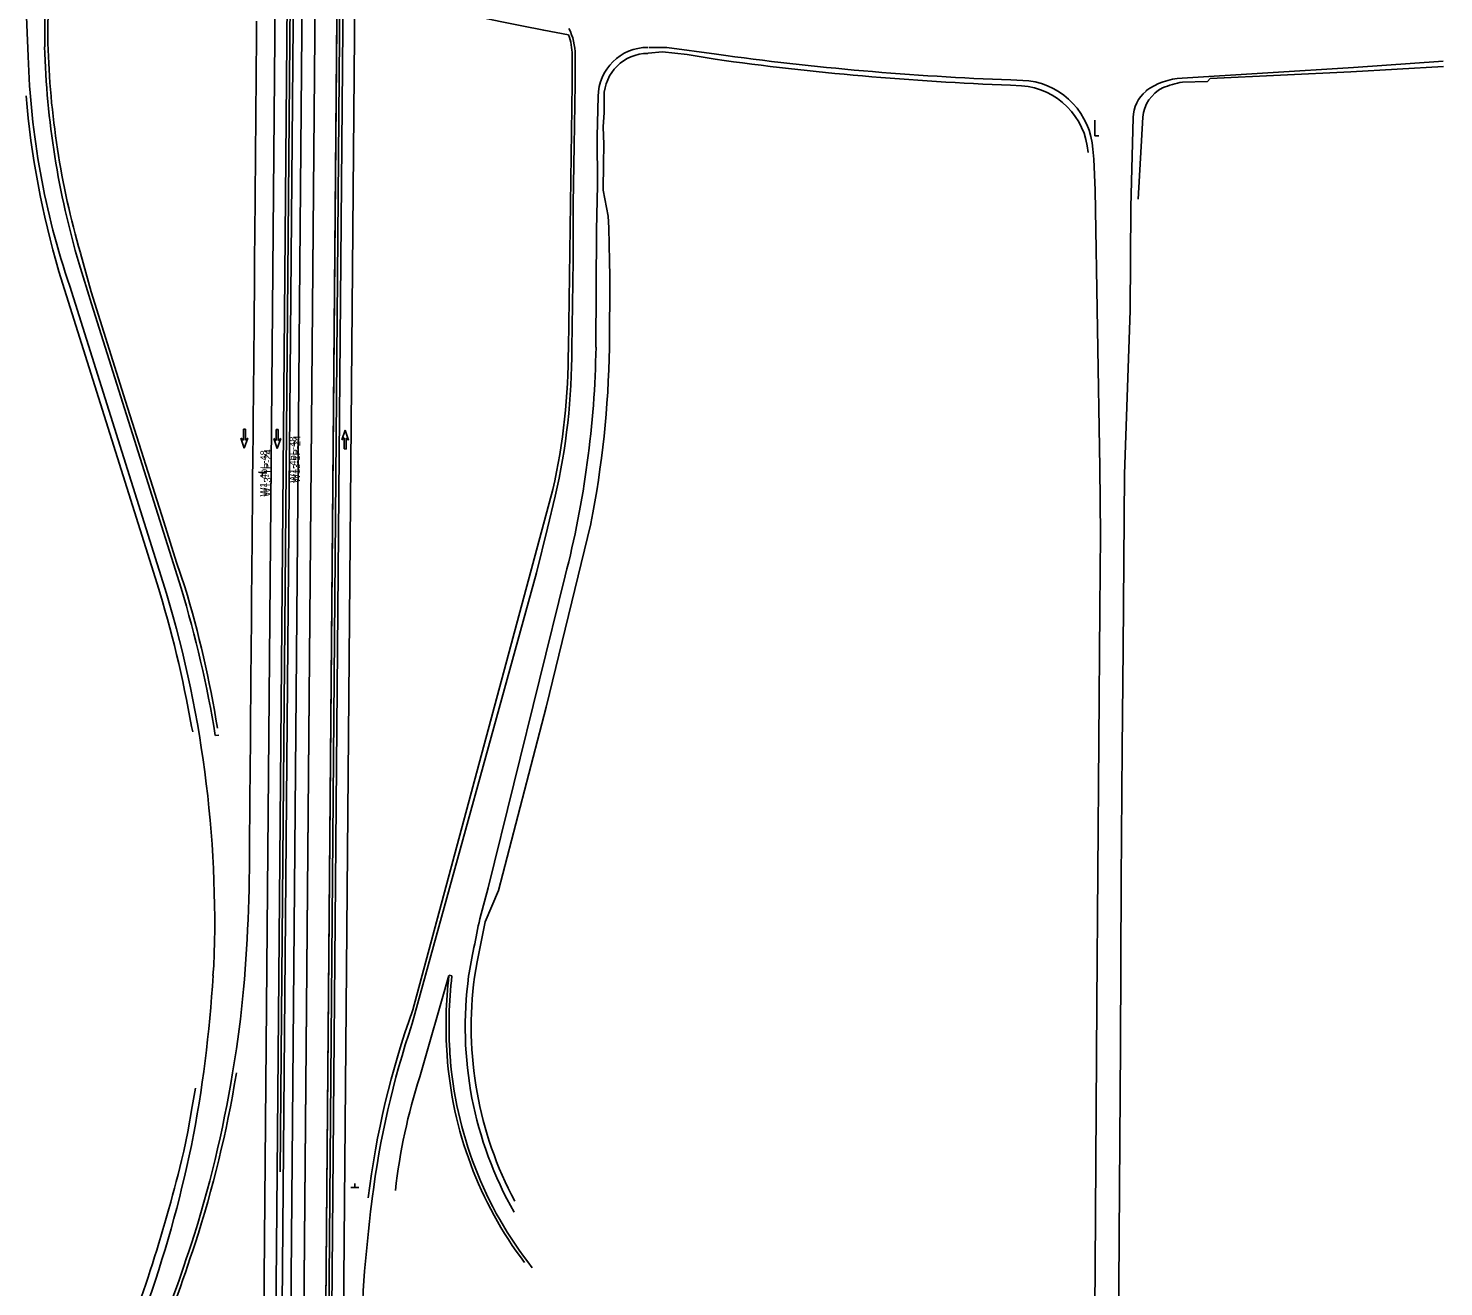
# Model space of a CAD drawing. Extents: x 1691089 to 1704871, y 694247 to 736350.
# Drawn here: x 1701130 to 1702547, y 710464 to 711724 of the extents above; entities that cross this region are included whole.
import ezdxf

# ---------------------------------------------------------------- set-up
doc = ezdxf.new("R2010")
doc.units = 0
for name, color, linetype in [('MT_P_Cells', 7, 'Continuous'), ('MT_P_Channelizing_Line', 7, 'Continuous'), ('MT_P_Drums', 7, 'Continuous'), ('MT_P_Edge_Line', 7, 'Continuous'), ('MT_P_PCB', 7, 'Continuous'), ('MT_P_Work_Area', 7, 'Continuous'), ('PM_X_Edge_Line', 7, 'Continuous'), ('PV_X_EOP', 7, 'Continuous'), ('PV_X_Shoulder', 7, 'Continuous'), ('RW_X_CL', 7, 'Continuous'), ('SC_Scratch1', 7, 'Continuous'), ('SC_Scratch2', 7, 'Continuous'), ('SN_P_Signs', 7, 'Continuous')]:
    doc.layers.add(name, color=color, linetype=linetype)

msp = doc.modelspace()

# ---------------------------------------------------------------- linework, layer by layer
at = {"layer": 'MT_P_Cells'}
for p, q in [((1701345.8, 711322.6), (1701345.7, 711311.6)), ((1701347.8, 711322.6), (1701345.8, 711322.6)), ((1701346.8, 711322.6), (1701346.8, 711322.6)), ((1701347.7, 711311.6), (1701347.8, 711322.6)), ((1701378.7, 711322.3), (1701378.6, 711311.3)), ((1701380.7, 711322.3), (1701378.7, 711322.3)), ((1701379.7, 711322.3), (1701379.7, 711322.3)), ((1701380.6, 711311.3), (1701380.7, 711322.3)), ((1701345.7, 711311.6), (1701343.2, 711313.6)), ((1701343.2, 711313.6), (1701346.6, 711303.6)), ((1701346.6, 711303.6), (1701350.2, 711313.6)), ((1701350.2, 711313.6), (1701347.7, 711311.6)), ((1701378.6, 711311.3), (1701376.2, 711313.4)), ((1701376.2, 711313.4), (1701379.6, 711303.3)), ((1701379.6, 711303.3), (1701383.1, 711313.3)), ((1701383.1, 711313.3), (1701380.6, 711311.3)), ((1701444.2, 711311.8), (1701447.7, 711321.7)), ((1701446.7, 711313.8), (1701444.2, 711311.8)), ((1701446.6, 711302.8), (1701446.7, 711313.8)), ((1701447.7, 711321.7), (1701447.7, 711321.7)), ((1701447.7, 711321.7), (1701451.1, 711311.7)), ((1701448.7, 711313.7), (1701448.6, 711302.7)), ((1701451.1, 711311.7), (1701448.7, 711313.7)), ((1701346.6, 711303.6), (1701346.6, 711303.6)), ((1701379.6, 711303.3), (1701379.6, 711303.3)), ((1701448.6, 711302.7), (1701446.6, 711302.8)), ((1701447.6, 711302.7), (1701447.6, 711302.7))]:
    msp.add_line(p, q, dxfattribs=at)
at = {"layer": 'MT_P_Channelizing_Line'}
msp.add_lwpolyline([(1701379.4, 710578.9), (1701376.8, 710278.9), (1701379.9, 709936.8)], dxfattribs=at)
at = {"layer": 'MT_P_Drums'}
msp.add_lwpolyline([(1701419.8, 715347.1), (1701419.8, 715347.1), (1701420.2, 715337.1), (1701420.6, 715327.2), (1701420.9, 715317.4), (1701421.1, 715307.5), (1701421.4, 715297.6), (1701421.5, 715287.7), (1701421.7, 715277.8), (1701421.8, 715267.8), (1701421.9, 715257.9), (1701422, 715248.1), (1701422, 715238), (1701422, 715228.1), (1701422, 715218.2), (1701422, 715208.2), (1701421.9, 715198.3), (1701421.9, 715188.3), (1701421.8, 715178.3), (1701421.7, 715168.3), (1701421.6, 715158.3), (1701421.5, 715148.4), (1701382.4, 710578.9)], dxfattribs=at)
at = {"layer": 'MT_P_Edge_Line'}
msp.add_line((1701445.2, 710328.3), (1701466.8, 712847.8), dxfattribs=at)
for points in [[(1701379.4, 710578.9), (1701418.5, 715148.4), (1701418.6, 715158.3), (1701418.7, 715168.3), (1701418.8, 715178.3), (1701418.9, 715188.3), (1701418.9, 715198.3), (1701419, 715208.2), (1701419, 715218.2), (1701419, 715228.1), (1701419, 715238), (1701419, 715248), (1701418.9, 715257.9), (1701418.8, 715267.8), (1701418.7, 715277.7), (1701418.5, 715287.6), (1701418.4, 715297.6), (1701418.1, 715307.4), (1701417.9, 715317.3), (1701417.6, 715327.1), (1701417.2, 715337), (1701416.8, 715346.9), (1701416.8, 715347)], [(1701414.4, 708961.6), (1701424.8, 709351.5), (1701474.5, 715147.9), (1701474.6, 715157.9), (1701474.7, 715167.9), (1701474.8, 715177.9), (1701474.9, 715187.9), (1701474.9, 715198), (1701475, 715208), (1701475, 715218), (1701475, 715228.1), (1701475, 715238.2), (1701475, 715248.3), (1701474.9, 715258.3), (1701474.8, 715268.4), (1701474.7, 715278.5), (1701474.5, 715288.6), (1701474.3, 715298.7), (1701474.1, 715308.8), (1701473.8, 715318.9), (1701473.5, 715329), (1701473.2, 715339.2), (1701472.7, 715349.3), (1701472.7, 715349.4)], [(1701367.9, 709936.9), (1701364.8, 710279), (1701390.1, 713227.6)]]:
    msp.add_lwpolyline(points, dxfattribs=at)
at = {"layer": 'MT_P_PCB'}
msp.add_line((1701429.8, 710278.5), (1701462.5, 714097.9), dxfattribs=at)
at = {"layer": 'MT_P_Work_Area'}
for points in [[(1701423.3, 715347.2), (1701423.7, 715337.2), (1701424.1, 715327.4), (1701424.4, 715317.5), (1701424.6, 715307.6), (1701424.9, 715297.7), (1701425, 715287.7), (1701425.2, 715277.8), (1701425.3, 715267.9), (1701425.4, 715257.9), (1701425.5, 715248.1), (1701425.5, 715238.1), (1701425.5, 715228.1), (1701425.5, 715218.1), (1701425.5, 715208.2), (1701425.4, 715198.3), (1701425.4, 715188.2), (1701425.3, 715178.3), (1701425.2, 715168.3), (1701425.1, 715158.3), (1701425, 715148.4), (1701383.7, 710328.9)], [(1701466.7, 715349.1), (1701466.7, 715349.1), (1701467.2, 715338.9), (1701467.5, 715328.8), (1701467.8, 715318.7), (1701468.1, 715308.6), (1701468.3, 715298.6), (1701468.5, 715288.5), (1701468.7, 715278.4), (1701468.8, 715268.3), (1701468.9, 715258.3), (1701469, 715248.3), (1701469, 715238.1), (1701469, 715228.1), (1701469, 715218), (1701469, 715208), (1701468.9, 715198.1), (1701468.9, 715188), (1701468.8, 715177.9), (1701468.7, 715167.9), (1701468.6, 715157.9), (1701468.5, 715148), (1701427.2, 710328.5)], [(1701459.4, 714084.3), (1701427.2, 710328.5), (1701383.7, 710328.9), (1701425, 715148.4)]]:
    msp.add_lwpolyline(points, dxfattribs=at)
at = {"layer": 'PM_X_Edge_Line'}
for points in [[(1701514.8, 710727.5), (1701639.2, 711178.9), (1701650.2, 711223.6), (1701658, 711255.4)], [(1701464.3, 710409.8), (1701464.4, 710419.8), (1701464.6, 710429.8), (1701464.9, 710439.7), (1701465.3, 710449.7), (1701465.8, 710459.7), (1701466.4, 710469.7), (1701467.1, 710479.6), (1701468, 710489.5), (1701469, 710499.5), (1701470, 710509.5), (1701471, 710519.5), (1701472, 710529.4), (1701473.1, 710539.4), (1701474.3, 710549.3), (1701474.7, 710552.4)]]:
    msp.add_lwpolyline(points, dxfattribs=at)
msp.add_arc((1702342.7, 710445.7), 874.5, 161.2053, 172.9888, dxfattribs=at)
at = {"layer": 'PV_X_EOP'}
for p, q in [((1701446.5, 715148.2), (1701323.4, 700783.8)), ((1701446.5, 715148.2), (1701323.4, 700783.8)), ((1701446.5, 715148.2), (1701323.4, 700783.8)), ((1701446.5, 715148.2), (1701323.4, 700783.8)), ((1701146.8, 711705.6), (1701146.8, 711766.9)), ((1701678, 711668.4), (1701677.9, 711697.3)), ((1702114.1, 711672.4), (1702132, 711671.5)), ((1701265.1, 711169.7), (1701172, 711465.7)), ((1701590.8, 710863.4), (1701667.8, 711175.7)), ((1701317.7, 711015.8), (1701321.1, 711016.3)), ((1701582.4, 710832.4), (1701590.8, 710863.4)), ((1701316.1, 710785.1), (1701315.3, 710775.7)), ((1701522.4, 710674.1), (1701551.5, 710775.7)), ((1701551.6, 710776), (1701554.5, 710775.4))]:
    msp.add_line(p, q, dxfattribs=at)
for points in [[(1701130.4, 711696), (1701127.8, 711751.1)], [(1701359, 711731.3), (1701358.9, 711721.3), (1701358.8, 711711.3), (1701358.8, 711708.9), (1701358.7, 711706.3), (1701358.7, 711701.3), (1701358.6, 711691.3), (1701358.5, 711681.3), (1701358.4, 711671.3), (1701358.4, 711661.3), (1701358.3, 711651.3), (1701358.2, 711641.3), (1701358.1, 711631.3), (1701358.1, 711621.3), (1701358, 711611.3), (1701357.9, 711601.3), (1701357.8, 711591.3), (1701357.7, 711581.3), (1701357.6, 711571.3), (1701357.5, 711561.3), (1701357.4, 711551.3), (1701357.4, 711541.3), (1701357.3, 711531.3), (1701357.2, 711521.3), (1701357.1, 711511.3), (1701357, 711501.3), (1701357, 711491.3), (1701356.9, 711481.3), (1701356.8, 711471.3), (1701356.7, 711461.3), (1701356.5, 711441.3), (1701356.5, 711431.3), (1701356.4, 711421.3), (1701356.2, 711401.3), (1701356.1, 711391.3), (1701356.1, 711381.3), (1701355.9, 711371.3), (1701355.8, 711361.3), (1701355.7, 711351.3), (1701355.6, 711341.3), (1701355.4, 711331.3), (1701355.4, 711321.3), (1701355.4, 711311.3), (1701355.2, 711301.2), (1701355.1, 711291.3), (1701355.1, 711289.9), (1701355.1, 711287.3), (1701355.1, 711284.3), (1701355, 711281.3), (1701355, 711271.3), (1701354.9, 711261.9)], [(1701751.8, 711704.9), (1701769.5, 711704.8), (1701819.5, 711698.1)], [(1702285.7, 711674.1), (1702457.2, 711684.7), (1702547, 711691.2)], [(1701678, 711668.4), (1701676.8, 711606.2), (1701675.8, 711548.6), (1701675.8, 711491.5), (1701674.6, 711403.5)], [(1701700.8, 711655.7), (1701699.8, 711616), (1701700.3, 711566.9), (1701699.4, 711522), (1701698.7, 711404.6)], [(1702236.5, 711634.6), (1702234.2, 711544.9), (1702233.5, 711441.5), (1702227.9, 711277.7), (1702226.4, 711103), (1702225.5, 711002.5), (1702224.4, 710870.4), (1702223.7, 710704.5), (1702222.7, 710562.6), (1702221.6, 710366.2), (1702220.3, 710180.7), (1702218.7, 709978.6), (1702217.3, 709834.2), (1702216.7, 709707.1), (1702216, 709519), (1702215.3, 709285.9), (1702216.9, 709101.8)], [(1702196.2, 711603), (1702197.1, 711593), (1702198.4, 711561.8), (1702203.2, 711284.2), (1702203.9, 711216.5), (1702203.6, 711180.6), (1702203.3, 711141.8), (1702200.2, 710747.3), (1702198.5, 710484), (1702195.7, 710156.1), (1702195.4, 710077.5), (1702194.4, 709958.4), (1702193.1, 709774.7), (1702191.7, 709594.1), (1702191.1, 709439.8), (1702190.5, 709333.9), (1702182.7, 709128.4)], [(1701283.4, 711163.4), (1701193.5, 711448.1), (1701181.3, 711488.3)], [(1701354.9, 711261.9), (1701354.8, 711251.9), (1701354.7, 711241.9), (1701354.6, 711231.9), (1701354.5, 711221.9), (1701354.4, 711211.9), (1701354.4, 711201.9), (1701354.3, 711191.9), (1701354.2, 711181.9), (1701354.1, 711171.9), (1701354, 711161.9), (1701353.9, 711151.9), (1701353.8, 711141.9), (1701353.8, 711131.9), (1701353.7, 711121.9), (1701353.6, 711111.9), (1701353.5, 711101.9), (1701353.5, 711091.9), (1701353.3, 711081.9), (1701353.2, 711071.9), (1701353.2, 711061.9), (1701353.1, 711051.9), (1701353, 711041.9), (1701352.9, 711031.9), (1701352.8, 711021.9), (1701352.7, 711011.9), (1701352.7, 711001.9), (1701352.6, 710991.9), (1701352.5, 710981.9), (1701352.4, 710971.9), (1701352.3, 710961.9), (1701352.3, 710951.9), (1701352.2, 710941.9), (1701352.1, 710931.9), (1701352, 710921.9), (1701351.9, 710911.9), (1701351.8, 710901.9), (1701351.7, 710891.9), (1701351.7, 710881.9), (1701351.6, 710871.9), (1701351.4, 710861.9), (1701351.1, 710851.8), (1701350.7, 710841.8), (1701350.4, 710831.8), (1701350, 710821.8), (1701349.5, 710811.8), (1701349, 710801.8), (1701348.3, 710791.8), (1701347.6, 710781.8), (1701346.7, 710771.7), (1701345.8, 710761.8), (1701344.9, 710751.8), (1701343.8, 710741.8), (1701342.7, 710731.8), (1701341.5, 710721.9), (1701340.3, 710711.9), (1701338.9, 710702), (1701337.3, 710692.1), (1701335.6, 710682.2), (1701334.9, 710678.2)], [(1701297.7, 710662.7), (1701294.5, 710644.4), (1701290.1, 710619), (1701286.1, 710599.7), (1701285.4, 710597.1)]]:
    msp.add_lwpolyline(points, dxfattribs=at)
for centre, radius, start, end in [((1701617.9, 711697.3), 60, 0.0027, 26.4067), ((1701990.6, 711728.5), 844.2, 181.5572, 196.5293), ((1701750.7, 711655), 49.9, 90.0908, 179.1381), ((1701904.8, 711717), 774.7, 181.5572, 198.9316), ((1702217.6, 714561.4), 2890.9, 262.0845, 267.9474), ((1702121.9, 711597.7), 74.5, 4.0408, 82.2515), ((1702288.6, 711608.1), 66.1, 92.5536, 126.4607), ((1702272.9, 711633.4), 36.4, 130.2121, 178.143), ((1701014.6, 711402.6), 660, 347.116, 0.0836), ((1700712.9, 711421), 986, 345.5917, 359.0473), ((1700176, 710829.4), 1141, 357.7771, 17.354), ((1700175.8, 710828.9), 1157, 9.2962, 16.8086), ((1703084.9, 710510.2), 1536.6, 167.8963, 170.0846), ((1700028.2, 710851.7), 1289.4, 348.9866, 356.6224), ((1701990.8, 710725.2), 439.2, 173.4452, 183.8222), ((1701943.8, 710724), 376, 172.2398, 209.5573), ((1701938.5, 710722.7), 386.8, 183.9675, 218.298), ((1700187.8, 710863.8), 1162, 342.0745, 350.8092), ((1702071.3, 710496.6), 576.9, 162.0779, 173.6518), ((1700032.2, 710871.6), 1289.4, 340.4478, 348.0836), ((1699818.1, 710945.7), 1508.1, 337.9462, 346.6374), ((1699464.5, 711101.9), 1923.4, 334.7451, 341.9596)]:
    msp.add_arc(centre, radius, start, end, dxfattribs=at)
at = {"layer": 'PV_X_Shoulder'}
for p, q in [((1701150, 711709.2), (1701150.4, 711767.4)), ((1701675, 711668.4), (1701674.9, 711697.3)), ((1702313.7, 711673.6), (1702454.6, 711680.3)), ((1702454.6, 711680.3), (1702547.4, 711685.9)), ((1701671.1, 711404), (1701675, 711668.4)), ((1702113.8, 711667.1), (1702124.7, 711666.4)), ((1702285.9, 711670.1), (1702311.1, 711670.9)), ((1702311.1, 711670.9), (1702313.7, 711673.6)), ((1702241.4, 711552.9), (1702246.2, 711635)), ((1702202.2, 711616.3), (1702198.2, 711616.3)), ((1701259.4, 711167.8), (1701161, 711480.6)), ((1701515.3, 710741.1), (1701655.6, 711262.3)), ((1701293.9, 711025), (1701295.1, 711019.4)), ((1701601, 710860.8), (1701587.9, 710829.2)), ((1701587.9, 710829.2), (1701579.7, 710789.3)), ((1701577.2, 710774), (1701579.7, 710789.3)), ((1701338.4, 710676.2), (1701338.9, 710678))]:
    msp.add_line(p, q, dxfattribs=at)
for points in [[(1701537.8, 711744.5), (1701559, 711740), (1701580.8, 711735.4), (1701602.7, 711730.9), (1701624.6, 711726.5), (1701646.5, 711722.1), (1701671.3, 711717.4)], [(1701750.9, 711699), (1701765.4, 711700.3), (1701790, 711697.7), (1701817.9, 711693.1)], [(1701706.8, 711655.7), (1701706.8, 711639.8), (1701705.9, 711625.5), (1701706.7, 711607.6), (1701706.3, 711588.4), (1701705.8, 711561.8), (1701710.9, 711535.9), (1701711.7, 711524.1), (1701712.4, 711490.7), (1701712.7, 711475.7), (1701712.2, 711404.1)], [(1702198.1, 711632.2), (1702198.2, 711616.3)], [(1701287, 711164.7), (1701278.9, 711189.1), (1701266, 711229.9), (1701227.8, 711350.8), (1701193.4, 711460.3), (1701182.5, 711499)], [(1701693.6, 711228), (1701648.8, 711044.3), (1701601, 710860.8)]]:
    msp.add_lwpolyline(points, dxfattribs=at)
for centre, radius, start, end in [((1701993.7, 711732.2), 844, 181.5572, 196.0361), ((1701617.9, 711697.3), 57, 0.0027, 20.5696), ((1701750.7, 711655), 43.9, 90.0908, 179.1348), ((1702218.6, 714560.1), 2894.9, 262.0443, 267.9264), ((1702119.6, 711594.6), 72, 4.0408, 85.9339), ((1702282.6, 711631.7), 36.6, 116.8859, 174.771), ((1702307.1, 711560.6), 111.6, 100.9466, 111.5787), ((1702008.5, 711730), 883.4, 184.7817, 196.3996), ((1701021.1, 711403), 650, 347.4957, 0.0836), ((1700712.3, 711420.7), 1000, 348.8913, 359.0482), ((1700175.6, 710830.4), 1135, 9.8732, 17.2906), ((1700223.6, 710844.7), 1110.6, 9.2511, 16.7465), ((1701990.8, 710725.2), 442.2, 173.4452, 183.8222), ((1701943.8, 710724), 370, 172.2398, 208.1335), ((1702342.7, 710445.7), 878.6, 160.3533, 172.9888), ((1701938.5, 710722.7), 389.8, 183.9675, 217.0019), ((1700189, 710865.9), 1165, 342.0728, 350.6282), ((1699445.1, 711109.2), 1947.6, 334.7855, 342.0001)]:
    msp.add_arc(centre, radius, start, end, dxfattribs=at)
at = {"layer": 'RW_X_CL'}
msp.add_line((1701323.4, 700783.8), (1701446.5, 715148.2), dxfattribs=at)
at = {"layer": 'SC_Scratch2'}
msp.add_lwpolyline([(1701391.8, 710278.8), (1701433.5, 715148.3), (1701433.6, 715158.2), (1701433.7, 715168.2), (1701433.8, 715178.2), (1701433.9, 715188.2), (1701433.9, 715198.2), (1701434, 715208.1), (1701434, 715218.1), (1701434, 715228.1), (1701434, 715238.1), (1701434, 715248.1), (1701433.9, 715258), (1701433.8, 715268), (1701433.7, 715277.9), (1701433.5, 715287.9), (1701433.4, 715297.9), (1701433.1, 715307.8), (1701432.9, 715317.7), (1701432.5, 715327.6), (1701432.2, 715337.6), (1701431.8, 715347.6), (1701431.8, 715347.6)], dxfattribs=at)
at = {"layer": 'SN_P_Signs'}
for p, q in [((1701360.8, 711279.5), (1701368.8, 711279.2)), ((1701364.8, 711279.4), (1701364.6, 711275.4)), ((1701461.2, 710563.2), (1701453.2, 710563.3)), ((1701457.2, 710563.2), (1701457.3, 710567.2))]:
    msp.add_line(p, q, dxfattribs=at)

# ---------------------------------------------------------------- texts
at = {"layer": 'SC_Scratch1'}
for s, p in [('W1-4bL-48', (1701398.5, 711268.9)), ('W13-1P-24', (1701402.3, 711268.8)), ('W1-4bL-48', (1701369.3, 711255.2)), ('W13-1P-24', (1701373.1, 711255.1))]:
    msp.add_text(s, height=7, rotation=89.5087, dxfattribs=at).set_placement(p)

doc.saveas('drawing.dxf')
